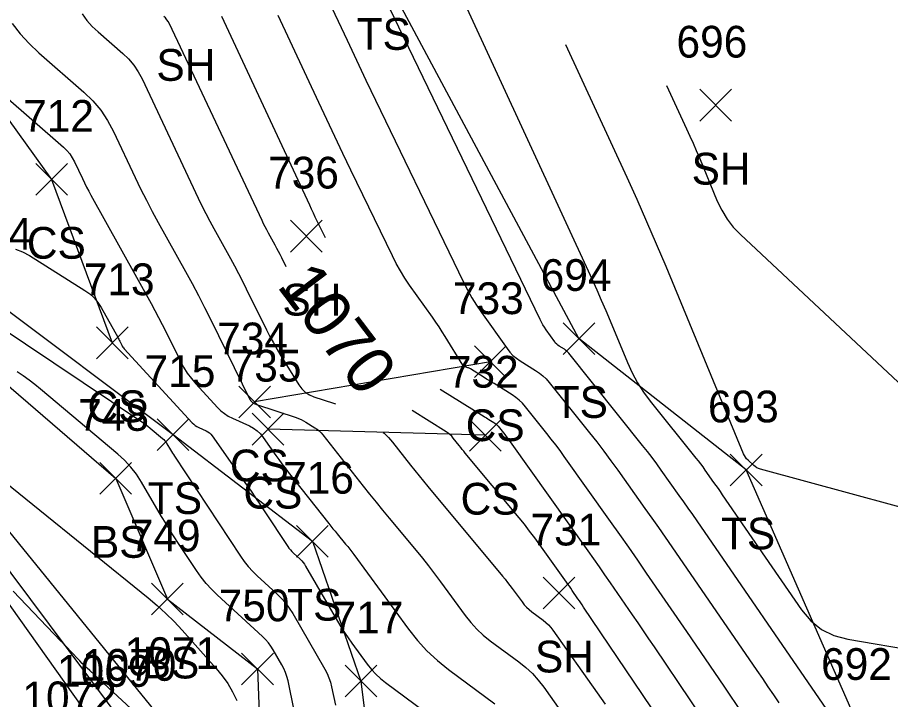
# Model space of a CAD drawing. Extents: x 1592612 to 1596497, y 111838 to 113741.
# Drawn here: x 1592870.8 to 1592925.8, y 113483.4 to 113526.4 of the extents above; entities that cross this region are included whole.
import ezdxf

# ---------------------------------------------------------------- set-up
doc = ezdxf.new("R2010")
doc.units = 0
for name, color, linetype in [('L_A', 7, 'Continuous'), ('L_I', 7, 'Continuous'), ('L_TIC', 7, 'Continuous'), ('LAWE', 7, 'Continuous'), ('LELB', 7, 'Continuous'), ('LSOGCMA', 7, 'Continuous'), ('LSOGCMA_T', 7, 'Continuous'), ('LSOGCMI', 7, 'Continuous')]:
    doc.layers.add(name, color=color, linetype=linetype)

msp = doc.modelspace()

# ---------------------------------------------------------------- linework, layer by layer
at = {"layer": 'L_TIC'}
for points in [[(1592913.814, 113519.836), (1592915.814, 113521.836)], [(1592915.814, 113519.836), (1592913.814, 113521.836)], [(1592871.973, 113515.163), (1592873.973, 113517.163)], [(1592873.973, 113515.163), (1592871.973, 113517.163)], [(1592888.031, 113511.584), (1592890.031, 113513.584)], [(1592890.031, 113511.584), (1592888.031, 113513.584)], [(1592875.794, 113504.866), (1592877.794, 113506.866)], [(1592877.794, 113504.866), (1592875.794, 113506.866)], [(1592905.203, 113505.134), (1592907.203, 113507.134)], [(1592907.203, 113505.134), (1592905.203, 113507.134)], [(1592899.625, 113503.673), (1592901.625, 113505.673)], [(1592901.625, 113503.673), (1592899.625, 113505.673)], [(1592884.768, 113501.138), (1592886.768, 113503.138)], [(1592886.768, 113501.138), (1592884.768, 113503.138)], [(1592885.616, 113499.423), (1592887.616, 113501.423)], [(1592887.616, 113499.423), (1592885.616, 113501.423)], [(1592879.629, 113499.08), (1592881.629, 113501.08)], [(1592881.629, 113499.08), (1592879.629, 113501.08)], [(1592899.305, 113499.042), (1592901.305, 113501.042)], [(1592901.305, 113499.042), (1592899.305, 113501.042)], [(1592915.743, 113496.853), (1592917.743, 113498.853)], [(1592917.743, 113496.853), (1592915.743, 113498.853)], [(1592876.011, 113496.321), (1592878.011, 113498.321)], [(1592878.011, 113496.321), (1592876.011, 113498.321)], [(1592888.409, 113492.364), (1592890.409, 113494.364)], [(1592890.409, 113492.364), (1592888.409, 113494.364)], [(1592903.943, 113489.098), (1592905.943, 113491.098)], [(1592905.943, 113489.098), (1592903.943, 113491.098)], [(1592879.268, 113488.72), (1592881.268, 113490.72)], [(1592881.268, 113488.72), (1592879.268, 113490.72)], [(1592884.948, 113484.322), (1592886.948, 113486.322)], [(1592886.948, 113484.322), (1592884.948, 113486.322)], [(1592891.469, 113483.552), (1592893.469, 113485.552)], [(1592893.469, 113483.552), (1592891.469, 113485.552)]]:
    msp.add_lwpolyline(points, dxfattribs=at)
at = {"layer": 'LAWE'}
msp.add_lwpolyline([(1592886.537, 113460.922), (1592877.744, 113481.574), (1592863.095, 113501.144), (1592852.902, 113518.209), (1592848.805, 113541.382), (1592835.879, 113571.623), (1592826.212, 113589.998), (1592821.08, 113603.103), (1592811.502, 113625.047), (1592801.909, 113656.496), (1592787.746, 113677.481), (1592769.551, 113701.793), (1592752.509, 113717.946)], dxfattribs=at)
at = {"layer": 'LELB'}
for points in [[(1592886.583, 113460.952), (1592879.778, 113482.315), (1592863.966, 113501.755), (1592853.366, 113518.29), (1592851.192, 113542.037), (1592841.019, 113567.093), (1592831.516, 113591.894), (1592821.816, 113602.808), (1592813.329, 113624.79), (1592804.232, 113657.067), (1592789.644, 113678.369), (1592770.935, 113703.549), (1592752.623, 113718.428)], [(1592886.43, 113460.851), (1592879.543, 113465.926), (1592876.137, 113481.194), (1592862.304, 113500.643), (1592852.529, 113517.932), (1592848.162, 113540.894), (1592835.177, 113571.255), (1592825.196, 113589.927), (1592820.421, 113603.303), (1592810.027, 113625.391), (1592799.468, 113655.332), (1592786.607, 113676.744), (1592768.899, 113700.806), (1592752.213, 113717.027)], [(1592885.411, 113547.376), (1592876.234, 113539.25), (1592867.617, 113532.911), (1592863.38, 113520.43), (1592865.405, 113513.944), (1592869.075, 113508.737), (1592880.629, 113500.08), (1592889.409, 113493.364), (1592892.469, 113484.552), (1592893.995, 113472.176), (1592892.484, 113467.779), (1592891.718, 113461.24)], [(1592918.957, 113461.096), (1592928.472, 113467.665), (1592923.872, 113481.628), (1592916.743, 113497.854), (1592906.203, 113506.134), (1592893.782, 113529.323)], [(1592853.127, 113529.053), (1592857.59, 113521.31), (1592858.606, 113515.284), (1592868.403, 113504.739), (1592877.011, 113497.321), (1592880.268, 113489.72), (1592885.949, 113485.322), (1592886.296, 113475.852), (1592890.02, 113471.216), (1592888.879, 113464.325)], [(1592867.005, 113524.43), (1592872.973, 113516.163), (1592876.794, 113505.866)], [(1592900.625, 113504.673), (1592885.768, 113502.138)], [(1592900.305, 113500.042), (1592886.616, 113500.423)]]:
    msp.add_lwpolyline(points, dxfattribs=at)
at = {"layer": 'LSOGCMA'}
for points in [[(1592899.015, 113527.211), (1592907.029, 113509.856), (1592907.324, 113509.208), (1592907.613, 113508.558), (1592907.895, 113507.904), (1592908.171, 113507.248), (1592909.261, 113504.618), (1592909.555, 113503.974), (1592909.892, 113503.354), (1592910.273, 113502.761), (1592910.696, 113502.192), (1592913.568, 113498.608), (1592913.716, 113498.421), (1592913.86, 113498.232), (1592914.002, 113498.042), (1592914.141, 113497.849), (1592914.693, 113497.075), (1592914.83, 113496.881), (1592914.967, 113496.686), (1592915.103, 113496.491), (1592915.238, 113496.296), (1592920.225, 113489.051), (1592920.807, 113488.353), (1592921.489, 113487.81), (1592922.269, 113487.42), (1592923.147, 113487.186), (1592927.59, 113486.431)], [(1592887.762, 113510.652), (1592887.478, 113511.229), (1592887.379, 113511.426), (1592887.278, 113511.622), (1592887.175, 113511.816), (1592887.069, 113512.009), (1592886.641, 113512.779), (1592886.536, 113512.973), (1592886.434, 113513.168), (1592886.335, 113513.364), (1592886.239, 113513.563), (1592880.392, 113525.97), (1592880.323, 113526.099), (1592880.242, 113526.219), (1592880.149, 113526.33), (1592880.044, 113526.431)], [(1592869.513, 113506.995), (1592878.54, 113500.973), (1592878.708, 113500.858), (1592878.873, 113500.738), (1592879.034, 113500.613), (1592879.191, 113500.485), (1592879.955, 113499.844), (1592880.038, 113499.768), (1592880.114, 113499.686), (1592880.182, 113499.598), (1592880.243, 113499.503), (1592880.473, 113499.113), (1592880.531, 113499.016), (1592880.591, 113498.919), (1592880.651, 113498.824), (1592880.713, 113498.729), (1592884.877, 113492.424), (1592885.113, 113492.089), (1592885.368, 113491.771), (1592885.643, 113491.468), (1592885.936, 113491.183), (1592887.147, 113490.071), (1592887.438, 113489.784), (1592887.705, 113489.477), (1592887.947, 113489.151), (1592888.165, 113488.805), (1592890.198, 113485.3), (1592890.336, 113485.038), (1592890.452, 113484.768), (1592890.546, 113484.489), (1592890.617, 113484.201), (1592890.858, 113483.034)], [(1592913.965, 113478.14), (1592906.498, 113489.218), (1592906.409, 113489.35), (1592906.319, 113489.481), (1592906.23, 113489.612), (1592906.14, 113489.743), (1592905.779, 113490.267), (1592905.689, 113490.398), (1592905.598, 113490.528), (1592905.507, 113490.658), (1592905.415, 113490.788), (1592903.734, 113493.148), (1592903.419, 113493.582), (1592903.097, 113494.009), (1592902.766, 113494.43), (1592902.427, 113494.845), (1592899.041, 113498.914), (1592898.944, 113499.031), (1592898.848, 113499.149), (1592898.752, 113499.268), (1592898.658, 113499.387), (1592898.281, 113499.864), (1592898.183, 113499.979), (1592898.076, 113500.084), (1592897.96, 113500.179), (1592897.835, 113500.264), (1592895.69, 113501.604)]]:
    msp.add_lwpolyline(points, dxfattribs=at)
at = {"layer": 'LSOGCMI'}
for points in [[(1592921.83, 113482.765), (1592913.649, 113494.65), (1592913.371, 113495.052), (1592913.092, 113495.453), (1592912.81, 113495.853), (1592912.528, 113496.252), (1592911.394, 113497.845), (1592911.108, 113498.241), (1592910.816, 113498.633), (1592910.519, 113499.02), (1592910.216, 113499.404), (1592905.569, 113505.203), (1592905.506, 113505.276), (1592905.437, 113505.342), (1592905.363, 113505.403), (1592905.283, 113505.457), (1592904.954, 113505.662), (1592904.874, 113505.716), (1592904.802, 113505.778), (1592904.736, 113505.846), (1592904.676, 113505.922), (1592904.134, 113506.686), (1592904.028, 113506.842), (1592903.929, 113507.001), (1592903.837, 113507.165), (1592903.752, 113507.333), (1592893.632, 113528.285)], [(1592890.254, 113527.79), (1592891.589, 113524.929), (1592891.884, 113524.299), (1592892.181, 113523.67), (1592892.481, 113523.041), (1592892.782, 113522.414), (1592898.927, 113509.692), (1592899.181, 113509.194), (1592899.454, 113508.708), (1592899.748, 113508.234), (1592900.062, 113507.772), (1592901.672, 113505.504), (1592901.848, 113505.28), (1592902.044, 113505.076), (1592902.26, 113504.893), (1592902.495, 113504.731), (1592903.473, 113504.124), (1592903.71, 113503.963), (1592903.931, 113503.784), (1592904.135, 113503.587), (1592904.323, 113503.371), (1592906.863, 113500.2), (1592907.322, 113499.62), (1592907.772, 113499.033), (1592908.213, 113498.44), (1592908.647, 113497.84), (1592910.363, 113495.429), (1592910.791, 113494.826), (1592911.216, 113494.22), (1592911.639, 113493.614), (1592912.06, 113493.005), (1592917.418, 113485.221), (1592917.767, 113484.711), (1592918.116, 113484.201), (1592918.463, 113483.69), (1592918.809, 113483.177)], [(1592874.889, 113526.583), (1592875.197, 113526.18), (1592875.537, 113525.803), (1592875.909, 113525.452), (1592877.457, 113524.101), (1592877.823, 113523.748), (1592878.147, 113523.362), (1592878.429, 113522.945), (1592878.669, 113522.496), (1592882.214, 113514.974), (1592882.447, 113514.49), (1592882.689, 113514.009), (1592882.938, 113513.533), (1592883.195, 113513.061), (1592884.241, 113511.181), (1592884.499, 113510.71), (1592884.752, 113510.235), (1592884.998, 113509.757), (1592885.238, 113509.276), (1592886.514, 113506.683), (1592886.725, 113506.267), (1592886.946, 113505.857), (1592887.177, 113505.451), (1592887.417, 113505.052), (1592888.549, 113503.221), (1592888.737, 113502.967), (1592888.958, 113502.757), (1592889.214, 113502.591), (1592889.504, 113502.467), (1592890.733, 113502.061), (1592890.871, 113502.011)], [(1592883.681, 113526.435), (1592884.258, 113525.186), (1592889.215, 113514.558), (1592889.332, 113514.307), (1592889.45, 113514.058), (1592889.569, 113513.808), (1592889.689, 113513.559), (1592890.201, 113512.5)], [(1592917.675, 113480.785), (1592915.349, 113484.236), (1592914.766, 113485.099), (1592914.181, 113485.959), (1592913.595, 113486.819), (1592913.006, 113487.676), (1592910.47, 113491.36), (1592909.907, 113492.175), (1592909.34, 113492.988), (1592908.771, 113493.798), (1592908.198, 113494.607), (1592905.277, 113498.71), (1592905.011, 113499.078), (1592904.74, 113499.442), (1592904.463, 113499.803), (1592904.182, 113500.159), (1592902.833, 113501.842), (1592902.648, 113502.055), (1592902.446, 113502.25), (1592902.228, 113502.427), (1592901.994, 113502.586), (1592900.857, 113503.292), (1592900.7, 113503.389), (1592900.543, 113503.486), (1592900.387, 113503.584), (1592900.23, 113503.682), (1592899.37, 113504.219), (1592899.329, 113504.242), (1592899.288, 113504.263), (1592899.246, 113504.282), (1592899.202, 113504.297), (1592899.025, 113504.356), (1592898.984, 113504.374), (1592898.947, 113504.398), (1592898.915, 113504.428), (1592898.888, 113504.464), (1592897.782, 113506.253), (1592897.587, 113506.563), (1592897.387, 113506.87), (1592897.182, 113507.173), (1592896.973, 113507.473), (1592895.533, 113509.5), (1592895.232, 113509.943), (1592894.951, 113510.398), (1592894.688, 113510.864), (1592894.445, 113511.341), (1592891.838, 113516.74), (1592891.327, 113517.802), (1592890.82, 113518.866), (1592890.317, 113519.931), (1592889.817, 113520.998), (1592887.256, 113526.488)], [(1592870.492, 113525.985), (1592870.996, 113525.327), (1592871.55, 113524.712), (1592872.157, 113524.139), (1592874.993, 113521.664), (1592875.562, 113521.115), (1592876.066, 113520.516), (1592876.504, 113519.868), (1592876.877, 113519.171), (1592878.238, 113516.282), (1592878.584, 113515.563), (1592878.942, 113514.85), (1592879.312, 113514.144), (1592879.694, 113513.443), (1592881.412, 113510.353), (1592881.823, 113509.603), (1592882.225, 113508.848), (1592882.617, 113508.088), (1592882.999, 113507.323), (1592885.47, 113502.301), (1592885.483, 113502.277), (1592885.498, 113502.254), (1592885.514, 113502.232), (1592885.532, 113502.211), (1592885.609, 113502.127), (1592885.628, 113502.109), (1592885.648, 113502.092), (1592885.669, 113502.078), (1592885.693, 113502.066), (1592885.788, 113502.023), (1592885.812, 113502.012), (1592885.836, 113502.002), (1592885.861, 113501.993), (1592885.886, 113501.985), (1592888.376, 113501.162), (1592888.536, 113501.104), (1592888.692, 113501.037), (1592888.843, 113500.96), (1592888.989, 113500.875), (1592889.568, 113500.513), (1592889.708, 113500.417), (1592889.838, 113500.311), (1592889.958, 113500.193), (1592890.069, 113500.065), (1592892.61, 113496.84), (1592893.014, 113496.331), (1592893.421, 113495.824), (1592893.832, 113495.321), (1592894.246, 113494.82), (1592895.938, 113492.787), (1592896.336, 113492.302), (1592896.726, 113491.81), (1592897.108, 113491.313), (1592897.482, 113490.809), (1592899.04, 113488.679), (1592899.387, 113488.239), (1592899.765, 113487.829), (1592900.173, 113487.449), (1592900.612, 113487.099), (1592902.425, 113485.76), (1592902.863, 113485.409), (1592903.268, 113485.027), (1592903.641, 113484.614), (1592903.982, 113484.169), (1592910.042, 113475.575)], [(1592948.516, 113485.775), (1592938.631, 113491.271), (1592936.963, 113492.135), (1592935.251, 113492.892), (1592933.496, 113493.544), (1592931.698, 113494.091), (1592917.634, 113497.908), (1592917.519, 113497.947), (1592917.411, 113497.999), (1592917.31, 113498.063), (1592917.216, 113498.141), (1592916.857, 113498.478), (1592916.772, 113498.566), (1592916.698, 113498.661), (1592916.635, 113498.764), (1592916.582, 113498.874), (1592911.693, 113510.666), (1592911.099, 113512.081), (1592910.49, 113513.489), (1592909.868, 113514.891), (1592909.232, 113516.287), (1592905.372, 113524.646)], [(1592868.052, 113523.134), (1592873.718, 113518.191), (1592873.927, 113517.988), (1592874.113, 113517.767), (1592874.274, 113517.529), (1592874.412, 113517.272), (1592874.913, 113516.207), (1592875.041, 113515.942), (1592875.173, 113515.68), (1592875.309, 113515.419), (1592875.45, 113515.161), (1592879.243, 113508.339), (1592879.481, 113507.905), (1592879.713, 113507.469), (1592879.94, 113507.029), (1592880.161, 113506.586), (1592881.088, 113504.703), (1592881.293, 113504.322), (1592881.523, 113503.958), (1592881.779, 113503.611), (1592882.061, 113503.282), (1592883.429, 113501.794), (1592883.637, 113501.589), (1592883.862, 113501.408), (1592884.104, 113501.251), (1592884.363, 113501.117), (1592885.435, 113500.63), (1592885.69, 113500.493), (1592885.921, 113500.326), (1592886.127, 113500.13), (1592886.309, 113499.905), (1592887.103, 113498.776), (1592887.293, 113498.509), (1592887.487, 113498.244), (1592887.685, 113497.982), (1592887.886, 113497.723), (1592890.44, 113494.483), (1592890.57, 113494.32), (1592890.701, 113494.156), (1592890.833, 113493.994), (1592890.967, 113493.833), (1592891.502, 113493.189), (1592891.635, 113493.027), (1592891.765, 113492.864), (1592891.893, 113492.698), (1592892.017, 113492.53), (1592895.461, 113487.819), (1592896.02, 113487.112), (1592896.627, 113486.454), (1592897.283, 113485.844), (1592897.987, 113485.282), (1592900.9, 113483.131)], [(1592911.729, 113522.081), (1592912.99, 113519.35), (1592913.198, 113518.893), (1592913.401, 113518.435), (1592913.6, 113517.975), (1592913.795, 113517.513), (1592914.92, 113514.799), (1592915.2, 113514.212), (1592915.537, 113513.664), (1592915.931, 113513.156), (1592916.382, 113512.688), (1592927.974, 113501.842), (1592928.875, 113501.094), (1592929.845, 113500.471), (1592930.886, 113499.973), (1592931.996, 113499.6), (1592937.007, 113498.24), (1592937.925, 113497.961), (1592938.821, 113497.628), (1592939.695, 113497.241), (1592940.547, 113496.8), (1592945.593, 113493.995)], [(1592870.691, 113511.765), (1592871.142, 113511.593), (1592871.573, 113511.359), (1592875.074, 113509.164), (1592875.38, 113508.945), (1592875.652, 113508.693), (1592875.889, 113508.409), (1592876.092, 113508.092), (1592877.137, 113506.212), (1592877.17, 113506.151), (1592877.203, 113506.09), (1592877.235, 113506.029), (1592877.266, 113505.967), (1592877.388, 113505.718), (1592877.42, 113505.657), (1592877.457, 113505.599), (1592877.498, 113505.544), (1592877.543, 113505.492), (1592881.839, 113500.821), (1592881.929, 113500.732), (1592882.026, 113500.654), (1592882.13, 113500.586), (1592882.242, 113500.528), (1592882.705, 113500.318), (1592882.816, 113500.258), (1592882.915, 113500.187), (1592883.004, 113500.102), (1592883.083, 113500.004), (1592885.255, 113496.916), (1592885.538, 113496.51), (1592885.818, 113496.102), (1592886.095, 113495.693), (1592886.369, 113495.281), (1592887.849, 113493.04), (1592887.93, 113492.925), (1592888.018, 113492.816), (1592888.112, 113492.712), (1592888.213, 113492.613), (1592888.63, 113492.231), (1592888.731, 113492.132), (1592888.822, 113492.026), (1592888.906, 113491.914), (1592888.981, 113491.794), (1592890.993, 113488.325), (1592891.204, 113487.971), (1592891.425, 113487.623), (1592891.655, 113487.281), (1592891.894, 113486.945), (1592892.868, 113485.612), (1592893.123, 113485.29), (1592893.4, 113484.99), (1592893.698, 113484.712), (1592894.019, 113484.456), (1592900.677, 113479.539)], [(1592888.622, 113480.928), (1592887.87, 113484.574), (1592887.805, 113484.837), (1592887.719, 113485.092), (1592887.613, 113485.339), (1592887.487, 113485.579), (1592886.941, 113486.521), (1592886.796, 113486.75), (1592886.635, 113486.967), (1592886.459, 113487.17), (1592886.266, 113487.361), (1592883.403, 113489.986), (1592883.041, 113490.339), (1592882.703, 113490.712), (1592882.388, 113491.105), (1592882.096, 113491.519), (1592880.978, 113493.212), (1592880.701, 113493.637), (1592880.43, 113494.065), (1592880.164, 113494.497), (1592879.904, 113494.932), (1592878.632, 113497.092), (1592878.315, 113497.581), (1592877.961, 113498.039), (1592877.568, 113498.464), (1592877.137, 113498.857), (1592872.262, 113502.949), (1592871.91, 113503.236), (1592871.551, 113503.513), (1592871.184, 113503.781), (1592870.809, 113504.038)], [(1592897.468, 113502.95), (1592900.228, 113501.227), (1592900.304, 113501.179), (1592900.38, 113501.132), (1592900.457, 113501.084), (1592900.533, 113501.037), (1592900.839, 113500.847), (1592900.913, 113500.797), (1592900.982, 113500.741), (1592901.046, 113500.679), (1592901.105, 113500.611), (1592901.532, 113500.079), (1592901.621, 113499.966), (1592901.708, 113499.852), (1592901.794, 113499.737), (1592901.878, 113499.62), (1592906.762, 113492.759), (1592907.116, 113492.259), (1592907.469, 113491.758), (1592907.819, 113491.255), (1592908.168, 113490.751), (1592909.558, 113488.731), (1592909.905, 113488.226), (1592910.25, 113487.72), (1592910.595, 113487.213), (1592910.938, 113486.705), (1592915.515, 113479.915)], [(1592893.866, 113500.222), (1592893.931, 113500.168), (1592894.204, 113499.902), (1592894.455, 113499.61), (1592895.592, 113498.167), (1592895.862, 113497.826), (1592896.135, 113497.487), (1592896.41, 113497.15), (1592896.687, 113496.814), (1592901.396, 113491.157), (1592901.553, 113490.966), (1592901.706, 113490.772), (1592901.857, 113490.576), (1592902.004, 113490.378), (1592902.618, 113489.539), (1592902.755, 113489.365), (1592902.903, 113489.204), (1592903.064, 113489.054), (1592903.237, 113488.916), (1592903.951, 113488.389), (1592904.124, 113488.251), (1592904.283, 113488.1), (1592904.43, 113487.937), (1592904.564, 113487.762), (1592907.351, 113483.81), (1592907.856, 113483.09)], [(1592868.143, 113498.622), (1592879.061, 113489.793), (1592879.626, 113489.317), (1592880.17, 113488.819), (1592880.693, 113488.299), (1592881.195, 113487.758), (1592883.336, 113485.353), (1592883.722, 113484.885), (1592884.068, 113484.393), (1592884.376, 113483.875), (1592884.645, 113483.333)], [(1592877.995, 113482.816), (1592875.379, 113485.215), (1592875.219, 113485.364), (1592875.061, 113485.517), (1592874.906, 113485.671), (1592874.753, 113485.829), (1592874.148, 113486.464), (1592873.997, 113486.623), (1592873.845, 113486.782), (1592873.694, 113486.941), (1592873.542, 113487.099), (1592870.555, 113490.226)]]:
    msp.add_lwpolyline(points, dxfattribs=at)

# ---------------------------------------------------------------- texts
at = {"layer": 'L_A'}
for s, p in [('TS', (1592892.192, 113524.323)), ('SH', (1592879.576, 113522.371)), ('SH', (1592913.302, 113515.836)), ('CS', (1592871.414, 113511.163)), ('SH', (1592887.519, 113507.584)), ('CS', (1592875.235, 113500.866)), ('TS', (1592904.612, 113501.134)), ('CS', (1592899.066, 113499.673)), ('CS', (1592884.209, 113497.138)), ('CS', (1592885.057, 113495.423)), ('TS', (1592879.038, 113495.08)), ('CS', (1592898.746, 113495.042)), ('TS', (1592915.153, 113492.853)), ('BS', (1592875.452, 113492.321)), ('TS', (1592887.818, 113488.364)), ('SH', (1592903.431, 113485.098)), ('BS', (1592878.709, 113484.72))]:
    msp.add_text(s, height=2, dxfattribs=at).set_placement(p)
at = {"layer": 'L_I'}
for s, p in [('696', (1592912.35, 113523.836)), ('712', (1592871.178, 113519.163)), ('736', (1592886.613, 113515.584)), ('714', (1592867.28, 113511.737)), ('694', (1592903.793, 113509.134)), ('713', (1592874.999, 113508.866)), ('733', (1592898.263, 113507.673)), ('734', (1592883.406, 113505.138)), ('735', (1592884.254, 113503.423)), ('715', (1592878.833, 113503.08)), ('732', (1592897.943, 113503.042)), ('748', (1592874.649, 113500.321)), ('693', (1592914.334, 113500.853)), ('716', (1592887.559, 113496.364)), ('749', (1592877.898, 113492.72)), ('731', (1592903.148, 113493.098)), ('750', (1592883.5, 113488.322)), ('717', (1592890.674, 113487.552)), ('1071', (1592877.573, 113485.314)), ('1070', (1592874.885, 113484.574)), ('692', (1592921.462, 113484.628)), ('1069', (1592873.311, 113484.194)), ('1072', (1592871.13, 113482.528))]:
    msp.add_text(s, height=2, dxfattribs=at).set_placement(p)
at = {"layer": 'LSOGCMA_T'}
msp.add_text('1070', height=3, rotation=307.1486, dxfattribs=at).set_placement((1592887.116, 113509.451))

doc.saveas('drawing.dxf')
